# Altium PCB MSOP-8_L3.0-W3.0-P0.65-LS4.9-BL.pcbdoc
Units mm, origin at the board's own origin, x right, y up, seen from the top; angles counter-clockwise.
Board outline 15.97 x 18.7 mm, 2 copper layers (Top Layer, Bottom Layer), stack 0 mm thick; 1 components, 0 nets, 8 pads, 0 vias.
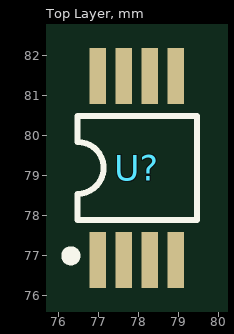
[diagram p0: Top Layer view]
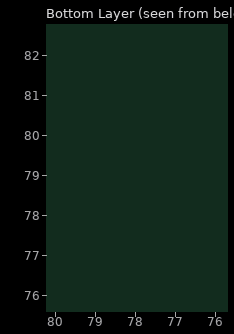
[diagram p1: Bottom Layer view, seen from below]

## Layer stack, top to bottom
Top Layer: signal copper (thickness not stored)
Bottom Layer: signal copper (thickness not stored)

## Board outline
85.82,69.85 69.85,69.85 69.85,88.547 85.82,88.547

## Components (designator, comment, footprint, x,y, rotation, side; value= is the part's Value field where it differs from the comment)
U? "" MSOP-8_L3.0-W3.0-P0.65-LS4.9-BL 77.97,79.198 r0 top

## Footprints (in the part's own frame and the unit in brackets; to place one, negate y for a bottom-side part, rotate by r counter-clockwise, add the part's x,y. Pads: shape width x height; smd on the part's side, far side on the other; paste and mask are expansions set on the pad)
MSOP-8_L3.0-W3.0-P0.65-LS4.9-BL [mil]
  rect 15.98x55 smd: 1(-38.39,-90.55) 2(-12.8,-90.55) 3(12.8,-90.55) 4(38.39,-90.55) 5(38.39,90.55) 6(12.8,90.55) 7(-12.8,90.55) 8(-38.39,90.55)
  silkscreen extent -70,-91 59,51

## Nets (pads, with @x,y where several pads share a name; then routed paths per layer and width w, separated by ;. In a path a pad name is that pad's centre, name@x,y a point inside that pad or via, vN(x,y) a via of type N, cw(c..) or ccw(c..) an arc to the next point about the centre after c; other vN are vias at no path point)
pads on no net: U?.1 U?.2 U?.3 U?.4 U?.5 U?.6 U?.7 U?.8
